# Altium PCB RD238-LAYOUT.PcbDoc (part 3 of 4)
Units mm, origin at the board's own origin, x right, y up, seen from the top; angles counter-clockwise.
Board outline 100 x 120 mm, 4 copper layers (Top Layer, GND2, POWER 3, Bottom Layer), stack 1.444 mm thick; 434 components, 174 nets, 1045 pads, 261 vias.
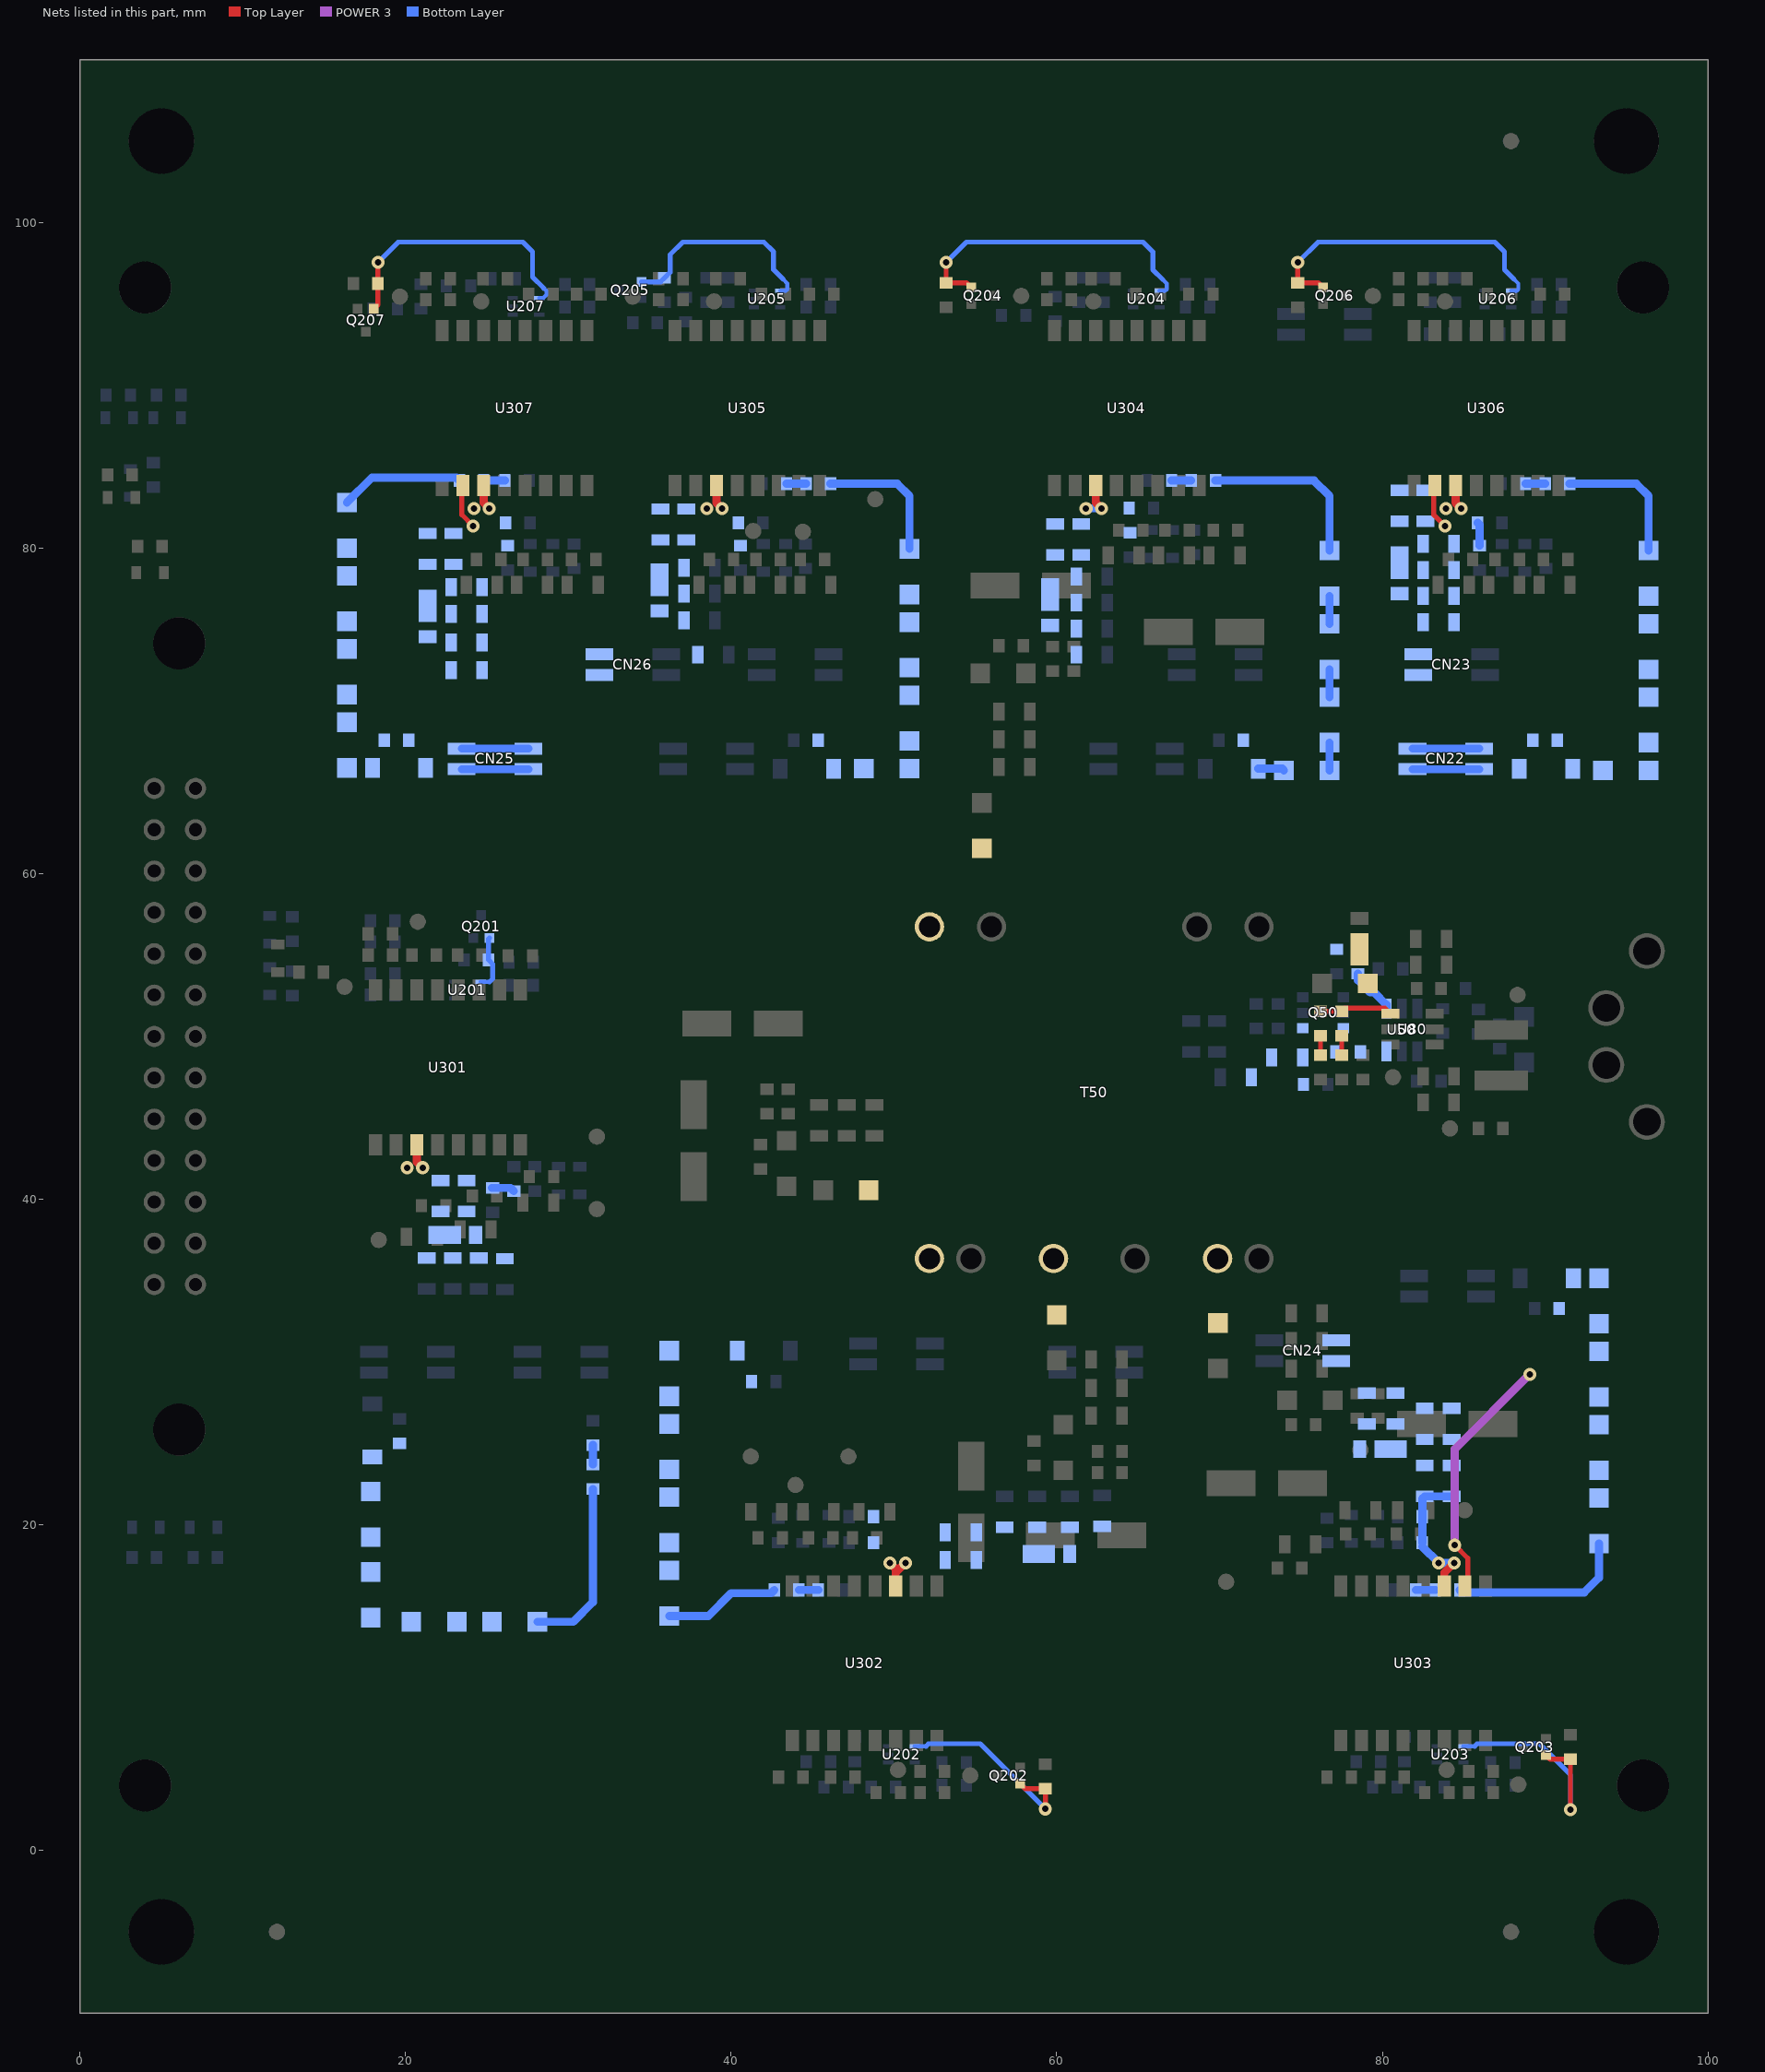
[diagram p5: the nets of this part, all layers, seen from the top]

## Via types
v1: diameter 0.8, hole 0.4, Top Layer to Bottom Layer, 261 vias

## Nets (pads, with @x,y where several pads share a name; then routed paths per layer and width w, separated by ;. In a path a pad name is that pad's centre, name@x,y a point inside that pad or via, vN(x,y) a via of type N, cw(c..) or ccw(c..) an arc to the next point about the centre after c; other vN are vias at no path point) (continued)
NetCN22_1: CN22.1 CN22.2 CN22.3 CN22.4 D376.2 R386.1 | length 8.2
  Bottom Layer w0.5: CN22.1@81.85,66.415 CN22.2@85.95,66.415 ; CN22.3@81.85,67.685 CN22.4@85.95,67.685
NetCN23_1: CN23.1 CN23.3 R366.1 R376.1 R396.1 R406.1 U306.10 | length 2.8
  Top Layer w0.3: U306.10@83.225,83.85 83.15,83.775 83.15,82.05 v1(83.85,81.35)
NetCN24_1: CN24.1 CN24.3 R363.1 R373.1 R393.1 R403.1 U303.10 | length 15.3
  Top Layer w0.3: v1(84.45,18.75) 85.25,17.95 85.25,16.425 U303.10@85.075,16.25
  POWER 3 w0.5: v1(84.45,18.75) 84.45,24.65 v1(89.05,29.25)
NetCN25_1: CN25.1 CN25.2 CN25.3 CN25.4 D377.2 R387.1 | length 8.2
  Bottom Layer w0.5: CN25.1@23.45,66.415 CN25.2@27.55,66.415 ; CN25.3@23.45,67.685 CN25.4@27.55,67.685
NetCN26_1: CN26.1 CN26.3 R367.1 R377.1 R397.1 R407.1 U307.10 | length 2.8
  Top Layer w0.3: U307.10@23.525,83.85 23.45,83.775 23.45,82.05 v1(24.15,81.35)
NetD50_2: D50.2 D51.2
NetD52_1: D52.1 T50.6
NetD53_1: D53.1 T50.7
NetD54_1: D54.1 T50.10
NetD55_1: D55.1 T50.13
NetD321_1: D321.1 D331.2
NetD321_2: D321.2 D371.1 R381.2
NetD322_1: D322.1 D332.2
NetD322_2: D322.2 D372.1 R382.2
NetD323_1: D323.1 D333.2
NetD323_2: D323.2 D373.1 R383.2
NetD324_1: D324.1 D334.2 | length 1.7
  Bottom Layer w0.5: D324.1@76.75,66.35 D334.2@76.75,68.05
NetD324_2: D324.2 D374.1 R384.2 | length 1.6
  Bottom Layer w0.5: D374.1@72.385,66.45 73.85,66.45 D324.2@73.95,66.35
NetD325_1: D325.1 D335.2
NetD325_2: D325.2 D375.1 R385.2
NetD326_1: D326.1 D336.2
NetD326_2: D326.2 D376.1 R386.2
NetD327_1: D327.1 D337.2
NetD327_2: D327.2 D377.1 R387.2
NetD331_1: D331.1 D341.2
NetD332_1: D332.1 D342.2
NetD333_1: D333.1 D343.2
NetD334_1: D334.1 D344.2 | length 1.7
  Bottom Layer w0.5: D334.1@76.75,70.85 D344.2@76.75,72.55
NetD335_1: D335.1 D345.2
NetD336_1: D336.1 D346.2
NetD337_1: D337.1 D347.2
NetD341_1: D341.1 D351.2
NetD342_1: D342.1 D352.2
NetD343_1: D343.1 D353.2
NetD344_1: D344.1 D354.2 | length 1.7
  Bottom Layer w0.5: D344.1@76.75,75.35 D354.2@76.75,77.05
NetD345_1: D345.1 D355.2
NetD346_1: D346.1 D356.2
NetD347_1: D347.1 D357.2
NetD351_1: D351.1 R351.1 | length 10.8
  Bottom Layer w0.5: D351.1@28.1,14.05 30.3,14.05 31.5,15.25 R351.1@31.5,22.2
NetD352_1: D352.1 R352.1 | length 7.1
  Bottom Layer w0.5: D352.1@36.2,14.4 38.6,14.4 40,15.8 42.45,15.8 R352.1@42.65,16
NetD353_1: D353.1 R353.1 | length 11.1
  Bottom Layer w0.5: R353.1@84.75,16 84.9,15.85 92.4,15.85 93.3,16.75 D353.1@93.3,18.85
NetD354_1: D354.1 R354.1 | length 10.7
  Bottom Layer w0.5: R354.1@69.75,84.15 75.8,84.15 76.75,83.2 D354.1@76.75,79.85
NetD355_1: D355.1 R355.1 | length 8.4
  Bottom Layer w0.5: R355.1@46.1,83.95 50.2,83.95 50.95,83.2 D355.1@50.95,79.95
NetD356_1: D356.1 R356.1 | length 8.5
  Bottom Layer w0.5: R356.1@91.5,83.95 92.016,83.95 95.6,83.95 96.35,83.2 D356.1@96.35,79.85
NetD357_1: D357.1 R357.1 | length 7.6
  Bottom Layer w0.5: D357.1@16.4,82.8 17.925,84.325 23.125,84.325 R357.1@23.3,84.15
NetD361_1: D361.1 R391.2 R401.2
NetD361_2: D361.2 R321.1 R331.1 R361.2 R371.2
NetD362_1: D362.1 R392.2 R402.2
NetD362_2: D362.2 R322.1 R332.1 R362.2 R372.2
NetD363_1: D363.1 R393.2 R403.2
NetD363_2: D363.2 R323.1 R333.1 R363.2 R373.2
NetD364_1: D364.1 R394.2 R404.2
NetD364_2: D364.2 R324.1 R334.1 R364.2 R374.2
NetD365_1: D365.1 R395.2 R405.2
NetD365_2: D365.2 R325.1 R335.1 R365.2 R375.2
NetD366_1: D366.1 R396.2 R406.2
NetD366_2: D366.2 R326.1 R336.1 R366.2 R376.2
NetD367_1: D367.1 R397.2 R407.2
NetD367_2: D367.2 R327.1 R337.1 R367.2 R377.2
NetQ50_3: Q50.3 R55.1
NetQ50_4: Q50.4 R56.1 R57.2
NetQ201_1: Q201.1 R231.2 U201.4 | length 3.4
  Bottom Layer w0.25: U201.4@24.612,53.35 25.15,53.35
  Bottom Layer w0.3: 25.15,53.35 25.35,53.55 25.35,54.45 R231.2@25.1,54.7 25.1,56 Q201.1@25.15,56.05
NetQ202_1: Q202.1 R232.2 U202.4 | length 12.7
  Top Layer w0.3: Q202.1@57.75,4.1 58.05,3.8 R232.2@59.3,3.8 v1(59.3,2.55)
  Bottom Layer w0.25: U202.4@51.274,6.4 51.97,6.4
  Bottom Layer w0.3: 51.97,6.4 52.12,6.55 55.3,6.55 v1(59.3,2.55)
NetQ203_1: Q203.1 R233.2 U203.4 | length 14.3
  Top Layer w0.3: Q203.1@90.05,5.85 90.3,5.6 R233.2@91.55,5.6 v1(91.55,2.5)
  Bottom Layer w0.25: U203.4@84.974,6.4 85.67,6.4
  Bottom Layer w0.3: 85.67,6.4 85.82,6.55 89.65,6.55 91.55,4.65 v1(91.55,2.5)
NetQ204_1: Q204.1 R234.2 U204.4 | length 19.5
  Top Layer w0.3: v1(53.2,97.55) R234.2@53.2,96.3 54.45,96.3 Q204.1@54.75,96
  Bottom Layer w0.25: U204.4@66.312,95.8 66.65,95.8 66.75,95.9 66.75,96.25 66.5,96.5
  Bottom Layer w0.3: v1(53.2,97.55) 54.45,98.8 65.3,98.8 65.9,98.2 65.9,97.1 66.5,96.5
NetQ205_1: Q205.1 R235.2 U205.4 | length 13.1
  Bottom Layer w0.25: U205.4@43.012,95.8 43.35,95.8 43.45,95.9 43.45,96.25 43.2,96.5
  Bottom Layer w0.3: Q205.1@34.5,96.35 35.65,96.35 R235.2@35.9,96.6 36.25,96.95 36.25,98.024 37.026,98.8 42,98.8 42.6,98.2 42.6,97.1 43.2,96.5
NetQ206_1: Q206.1 R236.2 U206.4 | length 19.5
  Top Layer w0.3: v1(74.8,97.55) R236.2@74.8,96.3 76.05,96.3 Q206.1@76.35,96
  Bottom Layer w0.25: U206.4@87.912,95.8 88.25,95.8 88.35,95.9 88.35,96.25 88.1,96.5
  Bottom Layer w0.3: v1(74.8,97.55) 76.05,98.8 86.9,98.8 87.5,98.2 87.5,97.1 88.1,96.5
NetQ207_1: Q207.1 R237.2 U207.4 | length 16.7
  Top Layer w0.3: Q207.1@18.05,94.7 18.3,94.95 v1(18.3,97.55)
  Bottom Layer w0.25: U207.4@28.212,95.35 28.45,95.35 28.65,95.55 28.65,95.8 28.5,95.95
  Bottom Layer w0.3: v1(18.3,97.55) 19.55,98.8 27.2,98.8 27.8,98.2 27.8,96.85 27.8,96.65 28.5,95.95
NetR52_1: R52.1 R54.2
NetR52_2: R52.2 U50.4 | length 3
  Bottom Layer w0.5: R52.2@78.5,53.85 78.5,53.46 79.254,52.706 79.494,52.706 80.25,51.95 U50.4@80.25,51.71
NetR55_2: R55.2 U50.3
NetR57_1: R57.1 R58.2
NetR80_1: R80.1 R81.2 | length 1.2
  Top Layer w0.3: R81.2@76.2,48.85 R80.1@76.2,50.05
NetR80_2: R80.2 R82.2 U80.4 | length 4.5
  Top Layer w0.3: R80.2@76.2,51.55 R82.2@77.5,51.55 77.7,51.75 80.15,51.75 U80.4@80.5,51.4
NetR82_1: R82.1 R83.2 | length 1.2
  Top Layer w0.3: R83.2@77.5,48.85 R82.1@77.5,50.05
NetR301_1: R301.1 R311.1 R321.2 R331.2 U301.11 | length 3
  Top Layer w0.5: U301.11@20.695,43.35 20.695,42.29 v1(21.046,41.939)
  Bottom Layer w0.5: R301.1@25.3,40.7 26.45,40.7 R311.1@26.65,40.5
  other v1: 20.096,41.939
NetR302_1: R302.1 R312.1 R322.2 R332.2 U302.11 | length 2.4
  Top Layer w0.5: v1(49.754,17.661) 50.105,17.31 50.105,17.062 ; U302.11@50.105,16.25 50.105,17.062 ; v1(50.704,17.661) 50.105,17.062
NetR303_1: R303.1 R313.1 R323.2 R333.2 U303.11 | length 8.6
  Top Layer w0.5: U303.11@83.805,16.25 83.805,17.062 v1(84.404,17.661)
  Bottom Layer w0.5: R313.1@82.45,18.665 v1(83.454,17.661) v1(84.404,17.661) ; R313.1@82.45,18.9 R303.1@82.45,20.5 82.45,21.6 R333.2@82.6,21.75 R323.2@84.25,21.75
NetR304_1: R304.1 R314.1 R324.2 R334.2 U304.11 | length 2.6
  Top Layer w0.5: U304.11@62.395,83.85 62.395,82.79 v1(62.746,82.439)
  Bottom Layer w0.5: v1(61.796,82.439) v1(62.746,82.439) v1@62.785,82.4
NetR305_1: R305.1 R315.1 R325.2 R335.2 U305.11 | length 1.6
  Top Layer w0.5: U305.11@39.095,83.85 39.095,82.79 v1(39.446,82.439)
  other v1: 38.496,82.439
NetR306_1: R306.1 R316.1 R326.2 R336.2 U306.11 | length 3
  Top Layer w0.5: U306.11@84.495,83.85 84.495,82.79 v1(84.846,82.439)
  Bottom Layer w0.5: R316.1@85.85,81.55 85.971,81.429 R306.1@85.971,80.15
  other v1: 83.896,82.439
NetR307_1: R307.1 R317.1 R327.2 R337.2 U307.11 | length 1.6
  Top Layer w0.5: U307.11@24.795,83.85 24.795,82.79 v1(25.146,82.439)
  other v1: 24.196,82.439
NetR341_1: R341.1 R351.2 | length 1.2
  Bottom Layer w0.5: R351.2@31.5,23.7 R341.1@31.5,24.9
NetR342_1: R342.1 R352.2 | length 1.2
  Bottom Layer w0.5: R352.2@44.15,16 R342.1@45.35,16
NetR343_1: R343.1 R353.2 | length 1.2
  Bottom Layer w0.5: R343.1@82.05,16 R353.2@83.25,16
NetR344_1: R344.1 R354.2 | length 1.2
  Bottom Layer w0.5: R344.1@67.05,84.15 R354.2@68.25,84.15
NetR345_1: R345.1 R355.2 | length 1.2
  Bottom Layer w0.5: R345.1@43.4,83.95 R355.2@44.6,83.95
NetR346_1: R346.1 R356.2 | length 1.2
  Bottom Layer w0.5: R346.1@88.8,83.95 R356.2@90,83.95
NetR347_1: R347.1 R357.2 | length 1.3
  Bottom Layer w0.5: R357.2@24.8,84.15 R347.1@26.1,84.15
pads on no net: ?.1 CN10.M1 CN10.M2 CN11.M1 CN11.M2

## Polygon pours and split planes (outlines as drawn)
NetC55_1 on Top Layer "Top Layer-NetC55_1" (solid, pour order 702): 74.95,54.75 75.95,54.75 76.2,55 76.2,56.65 76.4,56.85 78.95,56.85 79.1,57 79.1,57.55 79,57.65 74.95,57.65 74.7,57.4 74.7,56.85 74.7,55
NetC10_2 on Top Layer "Top Layer-NetC10_2" (solid, remove dead copper, pour order 691): 67.45,51.6 74.05,51.6 75,52.55 76.65,52.55 76.9,52.8 76.9,54.55 74.05,54.55 74.05,57.15 73.45,57.75 71.65,57.75 71.15,57.25 71.15,54.55 67.45,54.55
NetC332_2 on Top Layer "NONET_L04_P-001" (solid, remove dead copper, pour order 301): 59.071,30.9 62.292,30.9 62.45,30.742 62.45,25.85 62.2,25.6 59.85,25.6 59.05,24.8 56.4,24.8 56.05,24.45 53.8,24.45 53.8,25.629 55.421,27.25 58.1,27.25 58.75,27.9 58.75,30.579
NetC333_2 on Top Layer "NONET_L04_P-001" (solid, remove dead copper, pour order 268): 19 vertices, not listed, extent 69.002,15.75 74.75,33.8
NetC321_1 on Top Layer "NONET_L04_P-001" (solid, remove dead copper, pour order 294): 24 vertices, not listed, extent 39.95,35.4 55.75,55.8
NetC324_1 on Top Layer "NONET_L04_P-001" (solid, remove dead copper, pour order 499): 44 vertices, not listed, extent 33.75,71.7 60.05,84.6
NetC323_1 on Top Layer "NONET_L04_P-001" (solid, remove dead copper, pour order 273): 27 vertices, not listed, extent 71.5,19.85 89.65,37.55
NetC324_1 on Top Layer "NONET_L04_P-001" (solid, remove dead copper, pour order 390): 34 vertices, not listed, extent 73.25,71.7 92.7,84.6
GND on Top Layer "NONET_L04_P-001" (solid, remove dead copper, pour order 621): 24 vertices, not listed, extent 64.45,92.6 76.65,99
NetC81_1 on Top Layer "NONET_L04_P-001" (solid, remove dead copper, pour order 543): 88.15,52.8 88.975,52.8 89.55,52.225 89.55,50.3 89.05,49.8 84.9,49.8 84.5,50.2 84.5,50.55 85.6,51.65 87,51.65
NetC324_1 on Top Layer "NONET_L04_P-001" (solid, remove dead copper, pour order 435): 32 vertices, not listed, extent 20.55,71.7 35.95,84.6
NetR307_1 on Top Layer "NONET_L04_P-001" (solid, remove dead copper, pour order 434): 25.246,82.039 25.506,82.299 25.506,82.699 25.196,83.009 25.196,84.439 25.146,84.489 24.446,84.489 24.396,84.439 24.396,83.089 24.196,82.889 24.096,82.889 23.796,82.589 23.796,82.309 24.066,82.039
NetC245_1 on Top Layer "NONET_L04_P-001" (solid, remove dead copper, pour order 508): 34.15,94.5 33.743,94.907 33.743,96.557 34.65,95.65 35.8,95.65 35.9,95.55 35.9,94.6 36.95,93.55 36.95,92.85 36.75,92.65 36,92.65
NetC245_2 on Top Layer "NONET_L04_P-001" (solid, remove dead copper, pour order 507): 36.7,96.55 36.95,96.8 39.25,96.8 39.45,96.6 39.45,95.05 38.9,94.5 37.55,94.5 36.7,95.35
NetC247_1 on Top Layer "NONET_L04_P-001" (solid, remove dead copper, pour order 653): 18 vertices, not listed, extent 17.3,92.621 22.65,96.45
NetC247_2 on Top Layer "NONET_L04_P-001" (solid, remove dead copper, pour order 652): 22.4,96.55 22.65,96.8 24.95,96.8 25.15,96.6 25.15,95.05 24.6,94.5 23.25,94.5 22.4,95.35
NetC324_2 on Top Layer "NONET_L04_P-001" (solid, remove dead copper, pour order 436): 30.85,80.3 30.85,80.5 30.75,80.6 28.45,80.6 28.35,80.5 28.35,75.15 28.55,74.95 30.7,74.95 30.9,75.15 30.9,76.55 30.35,77.1 30.35,78.7 30.55,78.9 30.55,80
NetC324_2 on Top Layer "NONET_L04_P-001" (solid, remove dead copper, pour order 437): 30.85,84.45 30.75,84.35 30.75,83.15 30.5,82.9 29.5,82.9 29.25,82.65 29.25,82.25 28.35,81.35 28.35,80.3 30.85,80.3 31.1,80.55 31.1,82.55 31.55,83 31.55,84.35 31.45,84.45
NetC324_1 on Top Layer "NONET_L04_P-001" (solid, remove dead copper, pour order 438): 25.75,84.45 25.65,84.35 25.65,82.1 25.3,81.75 25.1,81.75 24.15,80.8 24.15,80.35 24.25,80.25 24.85,80.25 26.5,81.9 26.5,84.35 26.4,84.45
NetC334_2 on Top Layer "NONET_L04_P-001" (solid, remove dead copper, pour order 439): 21 vertices, not listed, extent 25.25,74.9 28.044,80.75
NetC334_2 on Top Layer "NONET_L04_P-001" (solid, remove dead copper, pour order 445): 25.449,80.449 25.55,80.55 26.9,81.9 26.9,84.3 27.05,84.45 27.65,84.45 27.75,84.35 27.75,82.9 28.05,82.6 28.05,80.3 27.85,80.1 25.449,80.1
GND on Top Layer "NONET_L04_P-001" (solid, remove dead copper, pour order 619): 23 vertices, not listed, extent 41.2,93.875 55.081,99
NetC334_2 on Top Layer "NONET_L04_P-001" (solid, remove dead copper, pour order 503): 18 vertices, not listed, extent 39.55,74.9 42.1,80.75
NetC334_2 on Top Layer "NONET_L04_P-001" (solid, remove dead copper, pour order 514): 40.25,80.6 41.2,81.55 41.2,84.3 41.35,84.45 41.95,84.45 42.05,84.35 42.05,82.9 42.35,82.6 42.35,80.725 41.725,80.1 40.25,80.1
NetC324_1 on Top Layer "NONET_L04_P-001" (solid, remove dead copper, pour order 502): 40.369,81.056 39.991,81.056 39.185,80.25 39.15,80.25 38.55,80.25 38.45,80.35 38.45,80.8 39.4,81.75 39.6,81.75 39.95,82.1 39.95,84.35 40.05,84.45 40.7,84.45 40.8,84.35 40.8,81.486
NetR305_1 on Top Layer "NONET_L04_P-001" (solid, remove dead copper, pour order 647): 39.546,82.039 39.806,82.299 39.806,82.699 39.496,83.009 39.496,84.439 39.446,84.489 38.746,84.489 38.696,84.439 38.696,83.089 38.496,82.889 38.396,82.889 38.096,82.589 38.096,82.309 38.366,82.039
NetC324_2 on Top Layer "NETC324_2_L01_P646" (solid, pour order 646): 17 vertices, not listed, extent 42.65,80.092 45.85,84.45
NetC324_2 on Top Layer "NETC324_2_L01_P645" (solid, pour order 645): 44.944,80.6 42.7,80.6 42.65,80.55 42.65,75.25 42.95,74.95 44.5,74.95 44.75,75.2 44.75,80.106 44.944,80.3
NetC324_2 on Top Layer "NONET_L04_P-001" (solid, remove dead copper, pour order 391): 90.55,80.3 90.55,80.5 90.45,80.6 88.15,80.6 88.05,80.5 88.05,75.15 88.25,74.95 89.85,74.95 90.1,75.2 90.1,77.05 90.05,77.1 90.05,78.7 90.25,78.9 90.25,80
NetD50_2 on Top Layer "NONET_L04_P-001" (solid, remove dead copper, pour order 564): 78.123,54.377 78.098,54.377 77.9,54.575 77.9,56.05 78.15,56.3 79.05,56.3 79.275,56.075 79.275,55.475 79.85,54.9 79.85,53 79.55,52.7 78.65,52.7 78.5,52.85 78.5,54
no net on Top Layer "NONET_L04_P-001" (solid, remove dead copper, pour order 303): 49.654,18.061 49.394,17.801 49.394,17.401 49.704,17.091 49.704,15.661 49.754,15.611 50.454,15.611 50.504,15.661 50.504,17.011 50.704,17.211 50.804,17.211 51.104,17.511 51.104,17.791 50.834,18.061
NetCN11_23 on Top Layer "NONET_L04_P-001" (solid, remove dead copper, pour order 457): 1.75,80.35 1.95,80.55 3.75,80.55 3.85,80.45 3.85,72.75 7.8,68.8 7.8,61.5 7.56,61.26 2.14,61.26 1.75,61.65
NetD52_1 on Top Layer "NONET_L04_P-001" (solid, remove dead copper, pour order 472): 52.05,54.5 50.8,55.75 50.8,57.95 53.35,60.5 54.95,62.1 58.65,62.1 58.95,61.8 58.95,55.2 58.25,54.5
GND on Top Layer "NONET_L04_P-001" (solid, remove dead copper, pour order 604): 18 vertices, not listed, extent 57.45,0.95 76.7,7.5
GND on Top Layer "NONET_L04_P-001" (solid, remove dead copper, pour order 623): 22 vertices, not listed, extent 88.55,6.55 99,57.75
no net on Top Layer "NONET_L01_P609" (solid, pour order 609): 1,-1 1,-9 99,-9 99,-1
no net on Top Layer "NONET_L01_P607" (solid, pour order 607): 1,109 1,101 99,101 99,109
GND on Top Layer "NONET_L04_P-001" (solid, remove dead copper, pour order 603): 18 vertices, not listed, extent 1,1 43.1,19.9
NetC324_1 on Top Layer "NONET_L04_P-001" (solid, remove dead copper, pour order 521): 63.3,84.4 63.3,81.5 62.479,80.679 62.479,80.471 62.75,80.2 63.45,80.2 64.1,80.85 64.1,84.25 63.85,84.5 63.4,84.5 63.3,84.4 63.3,84.35
NetC324_1 on Top Layer "NONET_L04_P-001" (solid, remove dead copper, pour order 522): 19 vertices, not listed, extent 58.15,79 63.9,84.65
NetC324_1 on Top Layer "NONET_L04_P-001" (solid, remove dead copper, pour order 393): 85.45,84.45 85.35,84.35 85.35,82.1 85,81.75 84.8,81.75 83.85,80.8 83.85,80.35 83.95,80.25 84.55,80.25 86.2,81.9 86.2,84.35 86.1,84.45
NetC331_2 on Top Layer "NONET_L04_P-001" (solid, remove dead copper, pour order 292): 26 vertices, not listed, extent 21.6,34.05 49.475,44.25
NetR306_1 on Top Layer "NONET_L04_P-001" (solid, remove dead copper, pour order 389): 84.946,82.039 85.206,82.299 85.206,82.699 84.896,83.009 84.896,84.439 84.846,84.489 84.146,84.489 84.096,84.439 84.096,83.089 83.896,82.889 83.796,82.889 83.496,82.589 83.496,82.309 83.766,82.039
GND on Top Layer "NONET_L04_P-001" (solid, remove dead copper, pour order 537): 27 vertices, not listed, extent 79.65,44.6 83.7,57.7
NetC81_1 on Top Layer "NONET_L04_P-001" (solid, remove dead copper, pour order 542): 82.7,50.75 84.7,50.75 85.15,51.2 85.3,51.2 85.4,51.1 85.4,49.9 85.3,49.8 84.9,49.8 84.55,50.15 82.699,50.15 82.65,50.199 82.65,50.7
NetC10_2 on Top Layer "NONET_L04_P-001" (solid, remove dead copper, pour order 541): 83.25,52.5 82.7,51.95 82.7,51.2 82.8,51.1 83.8,51.1 84.025,51.325 84.025,52.225 83.75,52.5
NetC221_2 on Top Layer "NONET_L04_P-001" (solid, remove dead copper, pour order 540): 87.45,45.8 87.1,45.45 87.1,43.95 87.25,43.8 90,43.8 90.2,44 90.2,45.5 89.9,45.8
NetC84_2 on Top Layer "NONET_L04_P-001" (solid, remove dead copper, pour order 539): 88.85,48.2 84.25,48.2 84.05,48 84.05,45.1 83.65,44.7 83.65,44.05 83.9,43.8 86,43.8 86.2,44 86.2,45.8 86.85,46.45 88.55,46.45 88.95,46.85 88.95,48.1 88.9,48.15
NetC10_2 on Top Layer "NONET_L04_P-001" (solid, remove dead copper, pour order 536): 17 vertices, not listed, extent 82.7,51.1 87.2,56.5
NetC324_2 on Top Layer "NONET_L04_P-001" (solid, remove dead copper, pour order 523): 69.6,84.45 69.75,84.3 69.75,81.5 69.35,81.1 68.05,81.1 67.8,81.35 67.8,81.95 68.35,82.5 68.35,84.4 68.4,84.45 68.45,84.45
NetC334_2 on Top Layer "NONET_L04_P-001" (solid, remove dead copper, pour order 520): 18 vertices, not listed, extent 64.1,76.8 66.95,84.5
NetC324_1 on Top Layer "NONET_L04_P-001" (solid, remove dead copper, pour order 519): 29 vertices, not listed, extent 60.625,71.098 74.468,84.6
NetC324_2 on Top Layer "NONET_L04_P-001" (solid, remove dead copper, pour order 518): 26 vertices, not listed, extent 57.6,71.7 69.75,81.95
NetC334_2 on Top Layer "NONET_L04_P-001" (solid, remove dead copper, pour order 516): 56.5,81.95 56.65,81.8 56.65,79.6 57.7,78.55 57.7,76.85 56.85,76 56.85,65.15 56.55,64.85 56.55,63.95 56.35,63.75 54.75,63.75 54.6,63.9 54.6,81.75 54.8,81.95
NetC324_1 on Top Layer "NONET_L04_P-001" (solid, remove dead copper, pour order 515): 17 vertices, not listed, extent 57.05,63.1 61.05,72.75
NetC244_1 on Top Layer "NONET_L04_P-001" (solid, remove dead copper, pour order 492): 19 vertices, not listed, extent 56,92.9 60.15,96.05
NetC244_2 on Top Layer "NONET_L04_P-001" (solid, remove dead copper, pour order 491): 60.6,96.9 60.6,94.75 60.85,94.5 62.2,94.5 62.45,94.75 62.45,96.9 62.35,97 60.7,97 60.65,96.95
NetR304_1 on Top Layer "NONET_L04_P-001" (solid, remove dead copper, pour order 489): 62.846,82.039 63.106,82.299 63.106,82.699 62.796,83.009 62.796,84.439 62.746,84.489 62.046,84.489 61.996,84.439 61.996,83.089 61.796,82.889 61.696,82.889 61.396,82.589 61.396,82.309 61.666,82.039
NetC246_1 on Top Layer "NONET_L04_P-001" (solid, remove dead copper, pour order 400): 19 vertices, not listed, extent 77.6,92.9 81.75,96.05
GND on Top Layer "NONET_L04_P-001" (solid, remove dead copper, pour order 469): 24 vertices, not listed, extent 2.4,82.552 17.35,98
NetC221_2 on Top Layer "NONET_L04_P-001" (solid, remove dead copper, pour order 459): 4.7,79.75 4.85,79.6 7.6,79.6 7.75,79.75 7.75,81.3 7.4,81.65 4.95,81.65 4.7,81.4
GND on Top Layer "NONET_L04_P-001" (solid, remove dead copper, pour order 458): 4.85,78.7 4.85,77.35 5.2,77 7.6,77 7.75,77.15 7.75,78.65 7.55,78.85 5,78.85
NetC246_2 on Top Layer "NONET_L04_P-001" (solid, remove dead copper, pour order 399): 82.2,96.9 82.2,94.75 82.45,94.5 83.8,94.5 84.05,94.75 84.05,96.9 83.95,97 82.3,97 82.25,96.95
NetC334_2 on Top Layer "NONET_L04_P-001" (solid, remove dead copper, pour order 395): 20 vertices, not listed, extent 84.95,74.9 87.744,80.75
NetC334_2 on Top Layer "NONET_L04_P-001" (solid, remove dead copper, pour order 394): 85.149,80.449 85.25,80.55 86.6,81.9 86.6,84.3 86.75,84.45 87.35,84.45 87.45,84.35 87.45,82.9 87.75,82.6 87.75,80.3 87.55,80.1 85.149,80.1
NetC324_2 on Top Layer "NONET_L04_P-001" (solid, remove dead copper, pour order 392): 90.55,84.45 90.45,84.35 90.45,83.15 90.2,82.9 89.2,82.9 88.95,82.65 88.95,82.25 88.05,81.35 88.05,80.3 90.55,80.3 90.8,80.55 90.8,82.55 91.25,83 91.25,84.35 91.15,84.45
NetC322_1 on Top Layer "NONET_L04_P-001" (solid, remove dead copper, pour order 307): 17 vertices, not listed, extent 49.2,15.55 53.05,22.6
NetC332_2 on Top Layer "NONET_L04_P-001" (solid, remove dead copper, pour order 306): 31 vertices, not listed, extent 45.85,15.65 57.85,27.35
NetC322_1 on Top Layer "NONET_L04_P-001" (solid, remove dead copper, pour order 304): 48.4,18.55 48.6,18.75 48.6,19.75 48.7,19.85 50.65,19.85 50.75,19.75 50.75,19.528 49.25,18.028 49.25,15.75 49.15,15.65 48.5,15.65 48.4,15.75
NetC241_1 on Top Layer "NONET_L04_P-001" (solid, remove dead copper, pour order 374): 16.25,55.4 16,55.15 16,52.6 16.3,52.3 18.3,52.3 18.55,52.55 18.55,53.55 18,54.1 18,55.05 17.65,55.4
NetC241_2 on Top Layer "NONET_L04_P-001" (solid, remove dead copper, pour order 373): 18.9,56.7 18.9,54.25 19.15,54 20.5,54 20.75,54.25 20.75,56.7 20.525,56.925 19.125,56.925
NetC242_1 on Top Layer "NONET_L04_P-001" (solid, remove dead copper, pour order 372): 17 vertices, not listed, extent 52.35,4.2 56.5,7.2
NetC242_2 on Top Layer "NONET_L04_P-001" (solid, remove dead copper, pour order 371): 51.9,3.2 51.9,5.35 51.65,5.6 50.3,5.6 50.05,5.35 50.05,3.2 50.15,3.1 51.8,3.1 51.85,3.15
NetR301_1 on Top Layer "NONET_L04_P-001" (solid, remove dead copper, pour order 296): 21.146,41.539 21.406,41.799 21.406,42.199 21.096,42.509 21.096,43.939 21.046,43.989 20.346,43.989 20.296,43.939 20.296,42.589 20.096,42.389 19.996,42.389 19.696,42.089 19.696,41.809 19.966,41.539
NetC323_1 on Top Layer "NONET_L04_P-001" (solid, remove dead copper, pour order 271): 82.85,15.65 82.95,15.75 82.95,18.028 84.45,19.528 84.45,19.75 84.35,19.85 82.15,19.85 82.1,19.8 82.1,15.75 82.2,15.65
NetC321_1 on Top Layer "NONET_L04_P-001" (solid, remove dead copper, pour order 329): 17.15,34.3 17.4,34.05 20.05,34.05 20.45,34.45 20.45,38.3 21.35,39.2 21.35,40.1 21.6,40.35 21.6,41.1 19.1,41.1 18.6,41.6 18.6,43.85 18.5,43.95 17.85,43.95 17.15,43.25
NetC321_1 on Top Layer "NONET_L04_P-001" (solid, remove dead copper, pour order 328): 21.7,43.95 22.3,43.95 22.4,43.85 22.4,40.75 22,40.35 21.6,40.35 21.35,40.1 21.35,39.65 21.25,39.55 20.45,39.55 20.4,39.6 20.4,40.25 21.6,41.45 21.6,43.85 21.65,43.9
NetC331_2 on Top Layer "NONET_L04_P-001" (solid, remove dead copper, pour order 327): 19 vertices, not listed, extent 21.6,34.95 24.5,43.95
NetC322_2 on Top Layer "NONET_L04_P-001" (solid, remove dead copper, pour order 309): 20 vertices, not listed, extent 54,15.5 62.85,24.85
NetC322_1 on Top Layer "NONET_L04_P-001" (solid, remove dead copper, pour order 308): 40.3,24.6 40.1,24.4 40.1,19 40.3,18.8 41.9,18.8 42.05,18.95 42.05,24.4 41.85,24.6
NetC322_2 on Top Layer "11" (solid, remove dead copper, pour order 305): 44.15,17.4 45.15,18.4 45.15,24.775 44.825,25.1 43.05,25.1 42.75,24.8 42.75,19.825 42.75,15.75 42.85,15.65 44.05,15.65 44.15,15.75
NetD54_1 on Top Layer "NONET_L04_P-001" (solid, remove dead copper, pour order 302): 59.2,37.3 60.9,37.3 61.2,37 61.2,32.714 60.786,32.3 59.214,32.3 58.8,32.714 58.8,36.9
NetC321_2 on Top Layer "NONET_L04_P-001" (solid, remove dead copper, pour order 298): 18 vertices, not listed, extent 24.95,36.65 28.05,43.95
NetC321_1 on Top Layer "NONET_L04_P-001" (solid, remove dead copper, pour order 297): 28.8,38.85 28.2,38.25 28.2,36.8 28.35,36.65 29.6,36.65 29.95,37 29.95,41 29.7,41.25 28.95,41.25 28.8,41.1
NetC321_2 on Top Layer "NONET_L04_P-001" (solid, remove dead copper, pour order 295): 24 vertices, not listed, extent 32.633,43.05 44.05,51.6
NetD53_1 on Top Layer "NONET_L04_P-001" (solid, remove dead copper, pour order 291): 52.85,35.35 53.2,35.7 53.2,39.95 51.75,41.4 48.05,41.4 47.8,41.15 47.8,39.55 48.05,39.3 51.05,36.3 51.05,36.05 51.75,35.35
NetC243_1 on Top Layer "NONET_L04_P-001" (solid, remove dead copper, pour order 284): 88.35,3.75 88.55,3.75 88.75,3.95 88.75,6.55 88.65,6.65 87.3,6.65 86.75,7.2 86.25,7.2 86.05,7 86.05,6.05 86.5,5.6 86.5,4.55 86.6,4.45 87.65,4.45
NetC243_2 on Top Layer "NONET_L04_P-001" (solid, remove dead copper, pour order 283): 85.6,3.2 85.6,5.35 85.35,5.6 84,5.6 83.75,5.35 83.75,3.2 83.85,3.1 85.5,3.1 85.55,3.15
NetC323_1 on Top Layer "NONET_L04_P-001" (solid, remove dead copper, pour order 277): 21 vertices, not listed, extent 82.1,15.6 89.539,23.9
NetC333_2 on Top Layer "NONET_L04_P-001" (solid, remove dead copper, pour order 276): 79.25,23.3 79.25,20.2 78.9,19.85 78.9,19 79.25,18.65 79.3,18.7 81.15,18.7 81.15,18.95 81.2,19 81.2,20.05 81.4,20.25 81.4,23.3 81.05,23.65 79.5,23.65 79.25,23.4
NetC323_1 on Top Layer "NONET_L04_P-001" (solid, remove dead copper, pour order 275): 71.7,19.35 71.5,19.15 71.5,16.65 71.8,16.35 73.7,16.35 73.9,16.55 73.9,17.85 74.35,18.3 74.35,19.25 74.25,19.35
NetC323_2 on Top Layer "NONET_L04_P-001" (solid, remove dead copper, pour order 274): 34 vertices, not listed, extent 73.6,15.65 83.85,28.2
NetC333_2 on Top Layer "NONET_L04_P-001" (solid, remove dead copper, pour order 272): 18 vertices, not listed, extent 78.9,15.65 81.7,20
NetR303_1 on Top Layer "NONET_L04_P-001" (solid, remove dead copper, pour order 270): 83.354,18.061 83.094,17.801 83.094,17.401 83.404,17.091 83.404,15.661 83.454,15.611 84.154,15.611 84.204,15.661 84.204,17.011 84.404,17.211 84.504,17.211 84.804,17.511 84.804,17.791 84.534,18.061
NetD55_1 on Top Layer "NONET_L04_P-001" (solid, remove dead copper, pour order 267): 70.95,31.85 70.8,31.7 68.95,31.7 68.8,31.85 68.8,37.15 69.05,37.4 70.6,37.4 70.95,37.05
NetC322_1 on Top Layer "NONET_L04_P-001" (solid, remove dead copper, pour order 145): 61.65,15.7 61.85,15.5 65.65,15.5 65.9,15.75 65.9,37.05 65.7,37.25 64,37.25 63.65,36.9 63.65,21 62.9,20.25 62.9,18.45 61.65,17.2
NetR57_1 on Bottom Layer "Bottom Layer-NetR57_1" (solid, pour order 704): 71.6,47.3 71.7,47.2 72.304,47.2 72.299,47.804 72.593,48.1 73.5,48.1 73.5,48.7 73.45,48.75 72.2,48.75 71.6,48.15
NetC55_1 on Bottom Layer "Bottom Layer-NetC55_1" (solid, pour order 699): 26 vertices, not listed, extent 66.9,51.35 77.95,57.7
NetC55_1 on Bottom Layer "NETC55_1_L04_P697" (solid, pour order 697): 76.2,54.548 76.2,57.7
NetC10_2 on Bottom Layer "Bottom Layer-NetC10_2" (solid, pour order 696): 70.702,51.5 72.75,51.5 72.75,52.85 72.742,52.842 67.458,52.842 67.45,52.85 67.45,50.5 70.7,50.5 70.7,51.498
NetC323_2 on Bottom Layer "NONET_L04_P-001" (solid, remove dead copper, pour order 336): 22 vertices, not listed, extent 69.85,20.15 81.3,31.7
NetC322_2 on Bottom Layer "NETC322_2_L04_P668" (solid, pour order 668): 17 vertices, not listed, extent 42.5,20.4 61.15,31
GND on Bottom Layer "NONET_L04_P-001" (solid, remove dead copper, pour order 561): 24 vertices, not listed, extent 80.15,43.8 95,50.5
NetC10_2 on Bottom Layer "NONET_L04_P-001" (solid, remove dead copper, pour order 544): 19 vertices, not listed, extent 85.05,50.5 95,56.35
NetC324_2 on Bottom Layer "NETC324_2_L04_P654" (solid, pour order 654): 23 vertices, not listed, extent 25.95,71.7 36.817,78.9
NetCN23_1 on Bottom Layer "NETCN23_1_L04_P628" (solid, pour order 628): 17 vertices, not listed, extent 81.2,71.7 84.975,81.75
NetD365_1 on Bottom Layer "NETD365_1_L04_P679" (solid, pour order 679): 18 vertices, not listed, extent 34.985,72.675 38.3,76.55
NetCN19_1 on Bottom Layer "NETCN19_1_L04_P633" (solid, pour order 633): 17 vertices, not listed, extent 38.025,71.7 42.75,81.75
NetCN18_1 on Bottom Layer "NETCN18_1_L04_P673" (solid, pour order 673): 65.8,23.65 63.6,21.45 52.8,21.45 52.325,21.925 52.325,22.363 52.537,22.575 59.275,22.575 63.65,26.95 63.65,30.75 63.9,31 65.4,31 65.8,30.6
NetD362_1 on Bottom Layer "NETD362_1_L04_P688" (solid, pour order 688): 63.367,20.1 60.65,20.1 60.422,19.872 60.422,17.828 60.7,17.55 63.25,17.55 63.65,17.95 63.65,19.817
NetD362_2 on Bottom Layer "NETD362_2_L04_P687" (solid, pour order 687): 55.4,17.4 55.95,17.95 57.75,17.95 58.3,17.4 59.4,17.4 59.75,17.75 59.75,19.35 59.05,20.05 55,20.05 54.75,19.8 54.75,17.6 54.95,17.4
NetR302_1 on Bottom Layer "NETR302_1_L04_P670" (solid, pour order 670): 17 vertices, not listed, extent 48.4,15.45 53.55,20.95
NetC10_2 on Bottom Layer "NETC10_2_L04_P683" (solid, pour order 683): 80.4,53.3 80.2,53.1 80.2,52.812 80.512,52.5 80.75,52.5 80.85,52.4 80.85,51.2 80.95,51.1 81.45,51.1 81.551,51.201 81.551,53.149 81.4,53.3
NetC10_2 on Bottom Layer "NONET_L04_P-001" (solid, remove dead copper, pour order 559): 81.075,53.675 80.9,53.85 80.9,54.8 82.45,56.35 87.25,56.35 87.35,56.25 87.35,53.9 87.125,53.675 84.825,53.675
NetD327_1 on Bottom Layer "NONET_L04_P-001" (solid, remove dead copper, pour order 682): 16.9,71.45 17,71.35 17,68.9 16.85,68.75 15.9,68.75 15.8,68.85 15.8,71.35 15.9,71.45
NetD347_1 on Bottom Layer "NONET_L04_P-001" (solid, remove dead copper, pour order 513): 16.9,80.45 17,80.35 17,77.9 16.85,77.75 15.9,77.75 15.8,77.85 15.8,80.35 15.9,80.45
NetD337_1 on Bottom Layer "NONET_L04_P-001" (solid, remove dead copper, pour order 512): 16.9,75.95 17,75.85 17,73.4 16.85,73.25 15.9,73.25 15.8,73.35 15.8,75.85 15.9,75.95
NetD367_1 on Bottom Layer "NETD367_1_L04_P681" (solid, pour order 681): 20.35,74.862 22.888,74.862 23.116,74.634 23.116,71.916 22.925,71.725 20.475,71.725 20.1,72.1 20.1,74.612
NetD367_2 on Bottom Layer "NETD367_2_L04_P680" (solid, pour order 680): 23.3,79.3 23.294,79.306 20.306,79.306 20.05,79.05 20.05,76.1 20.65,75.5 23.05,75.5 23.2,75.65 23.2,76.72 23.19,76.729 23.19,78.49 23.45,78.75 23.45,79.15
NetD365_2 on Bottom Layer "NETD365_2_L04_P678" (solid, pour order 678): 35.25,80.85 35.106,80.706 35.106,77.294 35.3,77.1 36.65,77.1 36.95,76.8 37.3,76.8 37.5,77 37.5,79.67 37.8,79.97 37.8,80.73 37.68,80.85
NetCN16_1 on Bottom Layer "NONET_L04_P-001" (solid, remove dead copper, pour order 579): 29 vertices, not listed, extent 17.85,29.05 32.5,42.35
NetD361_2 on Bottom Layer "NETD361_2_L04_P677" (solid, pour order 677): 24.35,39.5 24.25,39.6 21,39.6 20.75,39.35 20.75,36.2 20.95,36 23.2,36 23.35,36.15 23.35,38.869 23.481,39 24.3,39 24.35,39.05
NetD361_1 on Bottom Layer "NETD361_1_L04_P676" (solid, pour order 676): 24.1,38.35 23.962,38.212 23.962,36.088 24.05,36 26.5,36 26.6,36.1 26.6,36.6 26.275,36.925 25.725,36.925 25.5,37.15 25.5,38.05 25.2,38.35 24.3,38.35
NetCN20_1 on Bottom Layer "NETCN20_1_L04_P675" (solid, pour order 675): 43.45,31.55 43.2,31.3 43.2,30.001 42.45,29.251 42.45,28.328 42.603,28.175 52.358,28.175 53.05,28.867 53.05,31.35 52.85,31.55
NetR305_1 on Bottom Layer "NETR305_1_L04_P636" (solid, pour order 636): 17 vertices, not listed, extent 35.1,79.8 41.192,84.6
NetC324_2 on Bottom Layer "NETC324_2_L04_P662" (solid, pour order 662): 20 vertices, not listed, extent 40.2,71.8 47.2,78.959
NetD366_2 on Bottom Layer "NETD366_2_L04_P630" (solid, pour order 630): 82.75,81.95 80.65,81.95 80.45,81.75 80.45,78.2 80.55,78.1 82.7,78.1 82.85,78.25 82.85,81.05 82.85,81.85
NetD366_1 on Bottom Layer "NETD366_1_L04_P629" (solid, pour order 629): 82.75,77.6 82.85,77.5 82.85,75.05 82.65,74.85 80.6,74.85 80.4,75.05 80.4,77.45 80.55,77.6
GND on Bottom Layer "NONET_L04_P-001" (solid, remove dead copper, pour order 661): 17.15,98 17.3,97.85 17.3,97.1 17.8,96.6 21.3,96.6 21.35,96.55 21.35,96.05 21.25,95.95 16.1,95.95 15.8,96.25 15.8,97.75 16.05,98
NetD327_2 on Bottom Layer "mx" (solid, pour order 660): 19 vertices, not listed, extent 15.75,65.737 19.1,68.7
NetR307_1 on Bottom Layer "NETR307_1_L04_P658" (solid, pour order 658): 18 vertices, not listed, extent 20.15,79.8 26.8,83.4
NetR307_1 on Bottom Layer "NETR307_1_L04_P659" (solid, pour order 659): 23.35,82 26.175,82 26.35,82.175 26.35,82.7 25.65,83.4 23.835,83.4 23.35,82.915
NetCN26_1 on Bottom Layer "NETCN26_1_L04_P655" (solid, pour order 655): 25.275,74.925 26.25,73.95 32.45,73.95 32.7,73.7 32.7,72 32.4,71.7 25.3,71.7 24.35,72.65 24.35,80.577 23.725,81.202 23.725,81.545 23.93,81.75 25.05,81.75 25.275,81.525
NetR305_1 on Bottom Layer "NETR305_1_L04_P637" (solid, pour order 637): 37.6,82.003 40.478,82.003 40.65,82.175 40.65,82.7 39.9,83.45 37.9,83.45 37.6,83.15
NetR306_1 on Bottom Layer "NETR306_1_L04_P632" (solid, pour order 632): 83.425,82.43 83.855,82 83.857,82.003 85.878,82.003 86.05,82.175 86.05,82.7 85.3,83.45 83.487,83.45 83.425,83.388 83.425,83.29
NetR306_1 on Bottom Layer "NETR306_1_L04_P631" (solid, pour order 631): 18 vertices, not listed, extent 80.5,79.8 86.592,84.6
NetC324_2 on Bottom Layer "NETC324_2_L04_P627" (solid, pour order 627): 17 vertices, not listed, extent 85.5,71.7 92.7,78.9
NetCN25_1 on Bottom Layer "NONET_L04_P-001" (solid, remove dead copper, pour order 626): 21.225,68.7 20,68.7 19.85,68.55 19.85,67.8 19.95,67.7 20.55,67.7 20.8,67.45 20.8,65.9 20.9,65.8 28.625,65.8 28.825,66 28.825,68.45 28.575,68.7
NetD363_1 on Bottom Layer "NONET_L04_P-001" (solid, remove dead copper, pour order 340): 78.71,24.15 78.9,24.34 78.9,24.525 78.9,25.75 79,25.85 81.075,25.85 81.4,26.175 81.4,26.7 81.15,26.95 77.425,26.95 77.2,26.725 77.2,24.9 77.95,24.15
NetD364_1 on Bottom Layer "NONET_L04_P-001" (solid, remove dead copper, pour order 601): 58.689,75.589 58.4,75.3 58.4,73.1 58.6,72.9 61.3,72.9 61.505,73.105 61.505,75.335 61.251,75.589
NetD364_2 on Bottom Layer "NONET_L04_P-001" (solid, remove dead copper, pour order 600): 59.45,79.9 58.9,79.35 58.9,76.4 59.15,76.15 60.75,76.15 61.25,76.15 61.55,76.45 61.55,78.75 62.1,79.3 62.1,79.85 62.05,79.9 62,79.9
NetD363_2 on Bottom Layer "NONET_L04_P-001" (solid, remove dead copper, pour order 338): 79.575,25.074 79.656,25.158 81.679,25.158 82.071,25.55 84.65,25.55 84.75,25.45 84.75,23.5 84.6,23.35 81.979,23.35 81.229,24.1 79.725,24.1 79.575,24.25
no net on Bottom Layer "NONET_L04_P-001" (solid, remove dead copper, pour order 486): 77.25,68.5 77.35,68.4 77.35,65.95 77.2,65.8 76.25,65.8 76.15,65.9 76.15,68.4 76.25,68.5
no net on Bottom Layer "NONET_L04_P-001" (solid, remove dead copper, pour order 487): 77.25,73 77.35,72.9 77.35,70.45 77.2,70.3 76.25,70.3 76.15,70.4 76.15,72.9 76.25,73
no net on Bottom Layer "NONET_L04_P-001" (solid, remove dead copper, pour order 488): 77.25,77.5 77.35,77.4 77.35,74.95 77.2,74.8 76.25,74.8 76.15,74.9 76.15,77.4 76.25,77.5
GND on Bottom Layer "NONET_L04_P-001" (solid, remove dead copper, pour order 618): 18 vertices, not listed, extent 88.55,7.998 99,57.75
NetR304_1 on Bottom Layer "NONET_L04_P-001" (solid, remove dead copper, pour order 578): 21 vertices, not listed, extent 59.4,80.6 64.95,84.6
NetCN22_1 on Bottom Layer "NONET_L04_P-001" (solid, remove dead copper, pour order 617): 81.05,66 81.3,65.75 88.65,65.75 88.85,65.95 88.85,67.5 89.05,67.7 89.35,67.7 89.55,67.9 89.55,68.55 89.4,68.7 81.3,68.7 81.05,68.45
NetCN14_1 on Bottom Layer "NONET_L04_P-001" (solid, remove dead copper, pour order 616): 62.05,66 62.3,65.75 69.65,65.75 69.85,65.95 69.85,67.5 70.05,67.7 70.35,67.7 70.55,67.9 70.55,68.55 70.4,68.7 62.3,68.7 62.05,68.45
NetCN17_1 on Bottom Layer "NONET_L04_P-001" (solid, remove dead copper, pour order 615): 35.65,66 35.9,65.75 43.25,65.75 43.45,65.95 43.45,67.5 43.65,67.7 43.95,67.7 44.15,67.9 44.15,68.55 44,68.7 35.9,68.7 35.65,68.45
no net on Bottom Layer "NONET_L04_P614" (solid, pour order 614): 1,109 1,101 99,101 99,109
no net on Bottom Layer "NONET_L04_P611" (solid, pour order 611): 1,-1 1,-9 99,-9 99,-1
NetR52_1 on Bottom Layer "NONET_L04_P-001" (solid, remove dead copper, pour order 566): 76.8,55.7 77.025,55.925 78.675,55.925 78.9,55.7 78.9,55.15 78.75,55 76.95,55 76.8,55.15 76.8,55.65
NetC55_2 on Bottom Layer "NONET_L04_P-001" (solid, remove dead copper, pour order 565): 71.9,50.05 73.85,50.05 73.95,50.15 73.95,50.8 73.9,50.85 71.95,50.85 71.85,50.75 71.85,50.1
GND on Bottom Layer "NONET_L04_P-001" (solid, remove dead copper, pour order 560): 79.7,57.65 79.4,57.35 79.4,53.7 79.45,53.65 80.05,53.65 80.1,53.7 80.1,54.75 81.65,56.3 81.65,57.5 81.5,57.65
NetQ50_4 on Bottom Layer "NONET_L04_P-001" (solid, remove dead copper, pour order 557): 74.85,50.75 74.7,50.6 74.7,46.85 74.85,46.7 75.4,46.7 75.5,46.8 75.5,50.6 75.35,50.75
NetQ50_3 on Bottom Layer "NONET_L04_P-001" (solid, remove dead copper, pour order 556): 76.15,50.75 75.95,50.55 75.95,48.8 76.1,48.65 77.35,48.65 77.45,48.75 77.45,49.4 77.95,49.9 77.95,50.65 77.85,50.75
NetR55_2 on Bottom Layer "NONET_L04_P-001" (solid, remove dead copper, pour order 554): 78.5,49.7 78.35,49.55 78.35,48.2 78.6,47.95 80.3,47.95 80.55,48.2 80.55,49.55 80.4,49.7
NetC324_2 on Bottom Layer "NONET_L04_P-001" (solid, remove dead copper, pour order 490): 19 vertices, not listed, extent 64.15,71.75 73.1,79.7
NetCN24_1 on Bottom Layer "NONET_L04_P-001" (solid, remove dead copper, pour order 337): 78.774,31.1 78.174,31.7 76.6,31.7 76.3,31.4 76.3,28.45 77.05,27.7 81.4,27.7 82.3,26.8 89.15,26.8 89.55,27.2 89.55,29.55 89.35,29.75 86.85,29.75 80.15,29.75 78.8,31.1
GND on Bottom Layer "NONET_L04_P-001" (solid, remove dead copper, pour order 530): 67.4,49.35 67.1,49.05 67.1,46.95 67.55,46.5 70.15,46.5 70.4,46.75 70.4,49.1 70.15,49.35
NetCN15_1 on Bottom Layer "NONET_L04_P-001" (solid, remove dead copper, pour order 525): 26 vertices, not listed, extent 62.35,71.85 68.75,81.75
NetD345_1 on Bottom Layer "NONET_L04_P-001" (solid, remove dead copper, pour order 497): 51.45,77.6 51.55,77.5 51.55,75.05 51.4,74.9 50.45,74.9 50.35,75 50.35,77.5 50.45,77.6
NetD335_1 on Bottom Layer "NONET_L04_P-001" (solid, remove dead copper, pour order 496): 51.45,73.1 51.55,73 51.55,70.55 51.4,70.4 50.45,70.4 50.35,70.5 50.35,73 50.45,73.1
NetD325_1 on Bottom Layer "NONET_L04_P-001" (solid, remove dead copper, pour order 495): 51.45,68.6 51.55,68.5 51.55,66.05 51.4,65.9 50.45,65.9 50.35,66 50.35,68.5 50.45,68.6
NetD325_2 on Bottom Layer "NONET_L04_P-001" (solid, remove dead copper, pour order 494): 45.9,65.9 46.05,65.75 48.6,65.75 48.75,65.9 48.75,67.8 47.9,68.65 45.241,68.65 45.073,68.482 45.073,67.927 45.25,67.75 45.7,67.75 45.9,67.55 45.9,67.25
NetD324_2 on Bottom Layer "NONET_L04_P-001" (solid, remove dead copper, pour order 485): 72,65.9 72.15,65.75 74.4,65.75 74.5,65.85 74.5,68.15 74,68.65 71.341,68.65 71.173,68.482 71.173,67.927 71.35,67.75 71.8,67.75 72,67.55 72,67.25
GND on Bottom Layer "NONET_L04_P-001" (solid, remove dead copper, pour order 483): 4.6,91 5.05,90.55 5.05,88.9 4.75,88.6 4.75,87.75 4.6,87.6 3.15,87.6 2.95,87.8 2.95,88.7 2.75,88.9 2.75,90.05 2.6,90.2 2.6,90.7 2.9,91
NetCN13_1 on Bottom Layer "NONET_L04_P-001" (solid, remove dead copper, pour order 482): 22.8,30.8 17.4,30.8 17.25,30.65 17.25,27.15 17.4,27 18.55,27 19.3,26.25 22.25,26.25 22.95,26.95 22.95,30.65
NetD321_2 on Bottom Layer "NONET_L04_P-001" (solid, remove dead copper, pour order 481): 19.327,25.377 19.25,25.3 19.25,24.65 19.2,24.6 17.5,24.6 17.35,24.45 17.35,21.35 17.45,21.25 19.9,21.25 20.25,21.6 20.25,25.25 20.123,25.377
NetC321_2 on Bottom Layer "NONET_L04_P-001" (solid, remove dead copper, pour order 480): 26.7,33.25 26.5,33.05 26.5,29.25 26.75,29 28.2,29 28.4,29.2 28.4,32.95 28.1,33.25
NetD346_1 on Bottom Layer "NONET_L04_P-001" (solid, remove dead copper, pour order 388): 96.85,77.5 96.95,77.4 96.95,74.95 96.8,74.8 95.85,74.8 95.75,74.9 95.75,77.4 95.85,77.5
NetC324_1 on Bottom Layer "NONET_L04_P-001" (solid, remove dead copper, pour order 451): 23 vertices, not listed, extent 55.05,55.65 65.75,73.55
NetD336_1 on Bottom Layer "NONET_L04_P-001" (solid, remove dead copper, pour order 387): 96.85,73 96.95,72.9 96.95,70.45 96.8,70.3 95.85,70.3 95.75,70.4 95.75,72.9 95.85,73
NetD326_1 on Bottom Layer "NONET_L04_P-001" (solid, remove dead copper, pour order 386): 96.85,68.5 96.95,68.4 96.95,65.95 96.8,65.8 95.85,65.8 95.75,65.9 95.75,68.4 95.85,68.5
